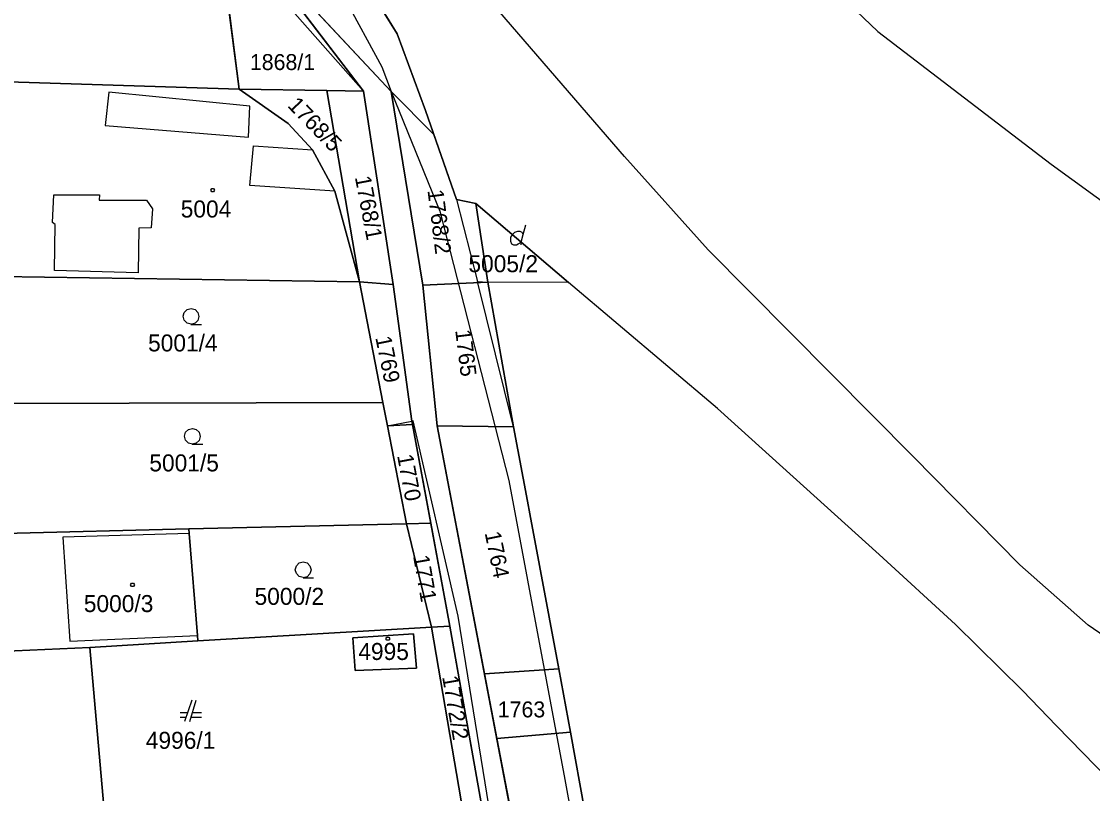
# Model space of a CAD drawing. Extents: x -263587 to -261993, y -1238795 to -1236748.
# Drawn here: x -262625.2 to -262524.5, y -1237560 to -1237487.3 of the extents above; entities that cross this region are included whole.
import ezdxf

# ---------------------------------------------------------------- set-up
doc = ezdxf.new("R2010")
doc.units = 0
doc.layers.add('Vrstva 1', color=7, linetype='Continuous')
doc.layers.add('Vrstva 3', color=7, linetype='Continuous')

msp = doc.modelspace()

# ---------------------------------------------------------------- linework, layer by layer
at = {"layer": 'Vrstva 1'}
for p, q in [((-262557.92, -1237475.57), (-262544.69, -1237488.29)), ((-262596.79, -1237477.25), (-262589.9, -1237488.51)), ((-262589.9, -1237488.51), (-262596.79, -1237477.25)), ((-262568.5, -1237500.03), (-262588.48, -1237476.89)), ((-262590.45, -1237493.93), (-262604.57, -1237478.84)), ((-262604.57, -1237478.84), (-262593.05, -1237493.89)), ((-262593.05, -1237493.89), (-262604.57, -1237478.84)), ((-262604.57, -1237478.84), (-262590.45, -1237493.93)), ((-262606.5, -1237480.16), (-262604.76, -1237493.69)), ((-262604.76, -1237493.69), (-262606.5, -1237480.16)), ((-262597.21, -1237480.76), (-262591.34, -1237491.61)), ((-262589.9, -1237488.51), (-262587.23, -1237495.71)), ((-262587.23, -1237495.71), (-262589.9, -1237488.51)), ((-262544.69, -1237488.29), (-262528.38, -1237500.77)), ((-262591.34, -1237491.61), (-262590.45, -1237493.93)), ((-262604.76, -1237493.69), (-262627.82, -1237492.98)), ((-262627.82, -1237492.98), (-262604.76, -1237493.69)), ((-262617.03, -1237493.98), (-262617.37, -1237497.12)), ((-262603.76, -1237495.29), (-262617.03, -1237493.98)), ((-262604.76, -1237493.69), (-262600.16, -1237496.94)), ((-262600.16, -1237496.94), (-262604.76, -1237493.69)), ((-262593.05, -1237493.89), (-262590.27, -1237512.08)), ((-262590.27, -1237512.08), (-262593.05, -1237493.89)), ((-262587.49, -1237512.15), (-262590.45, -1237493.93)), ((-262590.45, -1237493.93), (-262587.49, -1237512.15)), ((-262590.45, -1237493.93), (-262585.88, -1237505.19)), ((-262603.87, -1237498.23), (-262603.76, -1237495.29)), ((-262587.23, -1237495.71), (-262584.3, -1237504.1)), ((-262584.3, -1237504.1), (-262587.23, -1237495.71)), ((-262600.16, -1237496.94), (-262597.87, -1237499.42)), ((-262597.87, -1237499.42), (-262600.16, -1237496.94)), ((-262617.37, -1237497.12), (-262603.87, -1237498.23)), ((-262603.74, -1237502.77), (-262603.42, -1237499.04)), ((-262603.42, -1237499.04), (-262597.87, -1237499.42)), ((-262597.87, -1237499.42), (-262595.75, -1237503.29)), ((-262595.75, -1237503.29), (-262597.87, -1237499.42)), ((-262560.63, -1237508.84), (-262568.5, -1237500.03)), ((-262528.38, -1237500.77), (-262507.65, -1237515.81)), ((-262595.75, -1237503.29), (-262603.74, -1237502.77)), ((-262622.32, -1237506.26), (-262622.19, -1237503.64)), ((-262622.19, -1237503.64), (-262617.91, -1237503.66)), ((-262617.91, -1237503.66), (-262617.92, -1237504.14)), ((-262595.75, -1237503.29), (-262593.44, -1237511.83)), ((-262593.44, -1237511.83), (-262595.75, -1237503.29)), ((-262617.92, -1237504.14), (-262613.48, -1237504.14)), ((-262613.48, -1237504.14), (-262612.91, -1237504.97)), ((-262612.91, -1237504.97), (-262613.02, -1237506.76)), ((-262584.3, -1237504.1), (-262582.49, -1237504.46)), ((-262582.49, -1237504.46), (-262584.3, -1237504.1)), ((-262584.3, -1237504.1), (-262582.34, -1237511.82)), ((-262581.37, -1237511.87), (-262582.49, -1237504.46)), ((-262582.49, -1237504.46), (-262573.78, -1237511.91)), ((-262582.49, -1237504.46), (-262581.37, -1237511.87)), ((-262573.78, -1237511.91), (-262582.49, -1237504.46)), ((-262585.88, -1237505.19), (-262579.4, -1237530.54)), ((-262622.08, -1237506.45), (-262622.32, -1237506.26)), ((-262622.13, -1237510.78), (-262622.08, -1237506.45)), ((-262614.18, -1237506.8), (-262614.27, -1237510.98)), ((-262613.02, -1237506.76), (-262614.18, -1237506.8)), ((-262578.05, -1237507.37), (-262577.78, -1237506.47)), ((-262541.4, -1237528.26), (-262560.63, -1237508.84)), ((-262614.27, -1237510.98), (-262622.13, -1237510.78)), ((-262627.33, -1237511.35), (-262593.44, -1237511.83)), ((-262593.44, -1237511.83), (-262627.33, -1237511.35)), ((-262593.44, -1237511.83), (-262591.23, -1237523.21)), ((-262591.23, -1237523.21), (-262593.44, -1237511.83)), ((-262590.27, -1237512.08), (-262588.5, -1237524.94)), ((-262588.5, -1237524.94), (-262590.27, -1237512.08)), ((-262586.14, -1237525.4), (-262587.49, -1237512.15)), ((-262587.49, -1237512.15), (-262586.14, -1237525.4)), ((-262578.94, -1237525.5), (-262582.34, -1237511.82)), ((-262582.34, -1237511.82), (-262581.37, -1237511.87)), ((-262573.78, -1237511.91), (-262581.37, -1237511.87)), ((-262581.37, -1237511.87), (-262578.94, -1237525.5)), ((-262559.76, -1237523.75), (-262573.78, -1237511.91)), ((-262591.23, -1237523.21), (-262627.01, -1237523.3)), ((-262627.01, -1237523.3), (-262591.23, -1237523.21)), ((-262591.23, -1237523.21), (-262590.81, -1237525.39)), ((-262590.81, -1237525.39), (-262591.23, -1237523.21)), ((-262544.55, -1237537.49), (-262559.76, -1237523.75)), ((-262590.81, -1237525.39), (-262588.5, -1237524.94)), ((-262588.4, -1237524.92), (-262588.5, -1237524.94)), ((-262588.5, -1237524.94), (-262588.45, -1237525.28)), ((-262588.45, -1237525.28), (-262588.5, -1237524.94)), ((-262584.17, -1237543.32), (-262588.4, -1237524.92)), ((-262590.81, -1237525.39), (-262589.03, -1237534.6)), ((-262589.03, -1237534.6), (-262590.81, -1237525.39)), ((-262588.45, -1237525.28), (-262584.99, -1237543.91)), ((-262584.99, -1237543.91), (-262588.45, -1237525.28)), ((-262572.27, -1237598.01), (-262586.14, -1237525.4)), ((-262586.14, -1237525.4), (-262572.27, -1237598.01)), ((-262578.94, -1237525.5), (-262577.63, -1237532.47)), ((-262531.32, -1237538.46), (-262541.4, -1237528.26)), ((-262579.4, -1237530.54), (-262574.11, -1237558.68)), ((-262577.63, -1237532.47), (-262577.41, -1237533.66)), ((-262577.41, -1237533.66), (-262574.7, -1237548.27)), ((-262609.49, -1237535.1), (-262626.9, -1237535.53)), ((-262626.9, -1237535.53), (-262609.49, -1237535.1)), ((-262589.03, -1237534.6), (-262609.49, -1237535.1)), ((-262609.49, -1237535.1), (-262589.03, -1237534.6)), ((-262609.47, -1237535.51), (-262609.49, -1237535.1)), ((-262609.49, -1237535.1), (-262609.47, -1237535.51)), ((-262586.65, -1237544.35), (-262589.03, -1237534.6)), ((-262589.03, -1237534.6), (-262586.65, -1237544.35)), ((-262609.47, -1237535.51), (-262621.35, -1237535.87)), ((-262621.35, -1237535.87), (-262620.68, -1237545.67)), ((-262608.69, -1237545.14), (-262609.47, -1237535.51)), ((-262609.47, -1237535.51), (-262608.69, -1237545.14)), ((-262537.36, -1237544.1), (-262544.55, -1237537.49)), ((-262524.89, -1237544.14), (-262531.32, -1237538.46)), ((-262579.27, -1237573.38), (-262584.17, -1237543.32)), ((-262608.65, -1237545.63), (-262586.65, -1237544.35)), ((-262586.65, -1237544.35), (-262608.65, -1237545.63)), ((-262586.65, -1237544.35), (-262583.67, -1237561.97)), ((-262583.67, -1237561.97), (-262586.65, -1237544.35)), ((-262584.99, -1237543.91), (-262581.83, -1237561.75)), ((-262581.83, -1237561.75), (-262584.99, -1237543.91)), ((-262531.08, -1237550.31), (-262537.36, -1237544.1)), ((-262518.16, -1237548.81), (-262524.89, -1237544.14)), ((-262620.68, -1237545.67), (-262608.69, -1237545.14)), ((-262608.65, -1237545.63), (-262608.69, -1237545.14)), ((-262608.69, -1237545.14), (-262608.65, -1237545.63)), ((-262588.35, -1237544.98), (-262594.06, -1237545.34)), ((-262594.06, -1237545.34), (-262588.35, -1237544.98)), ((-262594.06, -1237545.34), (-262593.84, -1237548.41)), ((-262593.84, -1237548.41), (-262594.06, -1237545.34)), ((-262588.08, -1237548.21), (-262588.35, -1237544.98)), ((-262588.35, -1237544.98), (-262588.08, -1237548.21)), ((-262627.31, -1237546.63), (-262618.81, -1237546.26)), ((-262618.81, -1237546.26), (-262627.31, -1237546.63)), ((-262618.81, -1237546.26), (-262608.65, -1237545.63)), ((-262608.65, -1237545.63), (-262618.81, -1237546.26)), ((-262618.81, -1237546.26), (-262617.15, -1237565.12)), ((-262617.15, -1237565.12), (-262618.81, -1237546.26)), ((-262593.84, -1237548.41), (-262588.08, -1237548.21)), ((-262588.08, -1237548.21), (-262593.84, -1237548.41)), ((-262574.7, -1237548.27), (-262572.23, -1237561.68)), ((-262527.88, -1237553.63), (-262531.08, -1237550.31)), ((-262609.2, -1237551.22), (-262609.9, -1237553.22)), ((-262609.4, -1237553.22), (-262608.8, -1237551.22)), ((-262609.62, -1237552.42), (-262610.3, -1237552.42)), ((-262608.3, -1237552.42), (-262609.16, -1237552.42)), ((-262610.3, -1237552.82), (-262609.76, -1237552.82)), ((-262609.28, -1237552.82), (-262608.3, -1237552.82)), ((-262522.96, -1237558.68), (-262527.88, -1237553.63)), ((-262574.11, -1237558.68), (-262567.09, -1237597.19))]:
    msp.add_line(p, q, dxfattribs=at)
for points in [[(-262607.16, -1237503.06), (-262607.07, -1237503.21), (-262607.16, -1237503.36), (-262607.34, -1237503.36), (-262607.43, -1237503.21), (-262607.34, -1237503.06)], [(-262614.7, -1237540.2), (-262614.61, -1237540.35), (-262614.7, -1237540.5), (-262614.88, -1237540.5), (-262614.97, -1237540.35), (-262614.88, -1237540.2)], [(-262590.69, -1237545.28), (-262590.6, -1237545.43), (-262590.69, -1237545.58), (-262590.87, -1237545.58), (-262590.96, -1237545.43), (-262590.87, -1237545.28)]]:
    msp.add_lwpolyline(points, close=True, dxfattribs=at)
for points in [[(-262578.23, -1237508.36), (-262578.23, -1237508.09), (-262578.05, -1237507.37), (-262578.14, -1237507.19), (-262578.32, -1237507.1), (-262578.59, -1237507.1), (-262578.86, -1237507.19), (-262579.04, -1237507.37), (-262579.22, -1237507.64), (-262579.22, -1237508), (-262579.13, -1237508.27), (-262578.95, -1237508.36), (-262578.68, -1237508.36), (-262578.5, -1237508.27), (-262578.23, -1237508.09)], [(-262609.27, -1237515.82), (-262609.65, -1237515.72), (-262609.92, -1237515.45), (-262610.02, -1237515.08), (-262609.92, -1237514.71), (-262609.65, -1237514.44), (-262609.28, -1237514.34), (-262608.91, -1237514.44), (-262608.64, -1237514.71), (-262608.54, -1237515.09), (-262608.64, -1237515.47), (-262608.91, -1237515.74), (-262609.29, -1237515.84), (-262608.29, -1237515.84)], [(-262609.15, -1237527.11), (-262609.53, -1237527.01), (-262609.8, -1237526.74), (-262609.9, -1237526.37), (-262609.8, -1237526), (-262609.53, -1237525.73), (-262609.16, -1237525.63), (-262608.79, -1237525.73), (-262608.52, -1237526), (-262608.42, -1237526.38), (-262608.52, -1237526.76), (-262608.79, -1237527.03), (-262609.17, -1237527.13), (-262608.17, -1237527.13)], [(-262598.73, -1237539.67), (-262599.11, -1237539.57), (-262599.38, -1237539.3), (-262599.48, -1237538.93), (-262599.38, -1237538.56), (-262599.11, -1237538.29), (-262598.74, -1237538.19), (-262598.37, -1237538.29), (-262598.1, -1237538.56), (-262598, -1237538.94), (-262598.1, -1237539.32), (-262598.37, -1237539.59), (-262598.75, -1237539.69), (-262597.75, -1237539.69)]]:
    msp.add_lwpolyline(points, dxfattribs=at)
at = {"layer": 'Vrstva 3'}
for points in [[(-262690.64, -1237345.7), (-262667.54, -1237384.91), (-262660.8, -1237398.06), (-262641.01, -1237426.72), (-262626.71, -1237442.78), (-262600.19, -1237473.05), (-262596.79, -1237477.25), (-262589.9, -1237488.51), (-262587.23, -1237495.71), (-262586.436, -1237497.983), (-262590.45, -1237493.93), (-262604.57, -1237478.84), (-262593.05, -1237493.89), (-262637.35, -1237443.77), (-262664.8, -1237406.92), (-262667.59, -1237402.72), (-262673.98, -1237391.35), (-262674.03, -1237388), (-262685.64, -1237371.1), (-262690.37, -1237364.22)], [(-262572.23, -1237561.68), (-262573.602, -1237554.23), (-262574.7, -1237548.27), (-262577.41, -1237533.66), (-262577.63, -1237532.47), (-262578.94, -1237525.5), (-262581.37, -1237511.87), (-262582.49, -1237504.46), (-262584.3, -1237504.1), (-262586.436, -1237497.983), (-262587.23, -1237495.71), (-262589.9, -1237488.51), (-262596.79, -1237477.25)], [(-262581.83, -1237561.75), (-262584.932, -1237544.24), (-262584.99, -1237543.91), (-262586.728, -1237534.55), (-262588.45, -1237525.28), (-262588.5, -1237524.94), (-262590.27, -1237512.08), (-262593.05, -1237493.89), (-262604.57, -1237478.84), (-262590.45, -1237493.93), (-262587.49, -1237512.15), (-262586.14, -1237525.4), (-262581.685, -1237548.72), (-262580.522, -1237554.81), (-262578.276, -1237566.57)], [(-262606.5, -1237480.16), (-262604.76, -1237493.69), (-262600.16, -1237496.94), (-262597.87, -1237499.42), (-262595.75, -1237503.29), (-262593.44, -1237511.83), (-262591.23, -1237523.21), (-262590.81, -1237525.39), (-262589.03, -1237534.6), (-262586.65, -1237544.35), (-262583.67, -1237561.97)]]:
    msp.add_lwpolyline(points, dxfattribs=at)
for points in [[(-262637.35, -1237443.77), (-262593.05, -1237493.89), (-262596.5, -1237493.83), (-262604.76, -1237493.69), (-262606.5, -1237480.16), (-262634.06, -1237448.68), (-262648.03, -1237432.54), (-262658.49, -1237416.21), (-262664.8, -1237406.92)], [(-262604.76, -1237493.69), (-262596.5, -1237493.83), (-262593.44, -1237511.83), (-262595.75, -1237503.29), (-262597.87, -1237499.42), (-262600.16, -1237496.94)], [(-262596.5, -1237493.83), (-262593.05, -1237493.89), (-262590.27, -1237512.08), (-262593.44, -1237511.83)], [(-262590.45, -1237493.93), (-262586.436, -1237497.983), (-262584.3, -1237504.1), (-262582.49, -1237504.46), (-262581.37, -1237511.87), (-262587.49, -1237512.15)], [(-262593.44, -1237511.83), (-262590.27, -1237512.08), (-262588.5, -1237524.94), (-262588.45, -1237525.28), (-262590.81, -1237525.39), (-262591.23, -1237523.21)], [(-262587.49, -1237512.15), (-262581.37, -1237511.87), (-262578.94, -1237525.5), (-262586.14, -1237525.4)], [(-262590.81, -1237525.39), (-262588.45, -1237525.28), (-262586.728, -1237534.55), (-262589.03, -1237534.6)], [(-262586.14, -1237525.4), (-262578.94, -1237525.5), (-262577.63, -1237532.47), (-262577.41, -1237533.66), (-262574.7, -1237548.27), (-262581.685, -1237548.72)], [(-262589.03, -1237534.6), (-262586.728, -1237534.55), (-262584.99, -1237543.91), (-262584.932, -1237544.24), (-262586.65, -1237544.35)], [(-262586.65, -1237544.35), (-262584.932, -1237544.24), (-262581.83, -1237561.75), (-262583.67, -1237561.97)], [(-262581.685, -1237548.72), (-262574.7, -1237548.27), (-262573.602, -1237554.23), (-262580.522, -1237554.81)], [(-262580.522, -1237554.81), (-262573.602, -1237554.23), (-262572.23, -1237561.68), (-262571.84, -1237563.4), (-262571.44, -1237565.99), (-262578.276, -1237566.57)]]:
    msp.add_lwpolyline(points, close=True, dxfattribs=at)

# ---------------------------------------------------------------- texts
at = {"layer": 'Vrstva 1'}
for s, p in [('5004', (-262610.256, -1237505.78)), ('5005/2', (-262583.192, -1237510.93)), ('5001/4', (-262613.328, -1237518.39)), ('5001/5', (-262613.208, -1237529.68)), ('5000/3', (-262619.371, -1237542.92)), ('5000/2', (-262603.311, -1237542.24)), ('4995', (-262593.55, -1237547.43)), ('4996/1', (-262613.541, -1237555.79))]:
    msp.add_text(s, height=1.6, dxfattribs=at).set_placement(p)
at = {"layer": 'Vrstva 3'}
for s, p in [('1868/1', (-262603.749, -1237491.902)), ('1763', (-262580.431, -1237552.832))]:
    msp.add_text(s, height=1.5, dxfattribs=at).set_placement(p)
for s, rotation, p in [('1768/5', 314.03817, (-262600.288, -1237495.307)), ('1768/1', 280.74932, (-262593.881, -1237501.986)), ('1768/2', 277.08239, (-262587.044, -1237503.224)), ('1769', 281.49416, (-262591.956, -1237517.08)), ('1765', 276.9678, (-262584.439, -1237516.398)), ('1770', 280.52014, (-262589.904, -1237528.197)), ('1764', 281.43687, (-262581.669, -1237535.469)), ('1771', 279.88988, (-262588.399, -1237537.667)), ('1772/2', 279.83259, (-262585.665, -1237549.021))]:
    msp.add_text(s, height=1.5, rotation=rotation, dxfattribs=at).set_placement(p)

doc.saveas('drawing.dxf')
